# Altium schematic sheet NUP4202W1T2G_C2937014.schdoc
size 127 x 101 mm
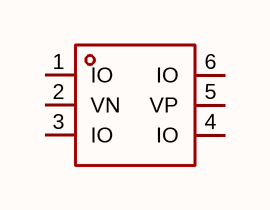
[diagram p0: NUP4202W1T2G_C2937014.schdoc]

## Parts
D?  nup4202w1t2g_c2937014  [SOT-363-6_L2.0-W1.3-P0.65-LS2.1-BL]  (value not drawn)

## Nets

Not connected (* = marked no-connect by the designer): D? 1(IO) 2(VN) 3(IO) 4(IO) 5(VP) 6(IO)

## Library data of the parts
D? = nup4202w1t2g_c2937014: 极性:单向;反向截止电压(Vrwm):5V;钳位电压:16V；17V;峰值脉冲电流(Ipp):4.5A@8/20us;峰值脉冲功率(Ppp):250W;击穿电压:9.5V;; Manufacturer: TECH PUBLIC(台舟); AddInBom: yes; ModelId: 600d0067f956474aba900c417738e59b; ModelName: SOT-363-6_L2.0-W1.25-LS2.1-BL; ModelTransform: 78.74,82.677,0,0,0,0,0,0,0; Polarity: 单向; Reverse Stand-Off Voltage (Vrwm): 5V; Peak Pulse Power Dissipation (Ppp): 250W; Voltage - Breakdown: 9.5V; Reverse Leakage Current (Ir): 100nA; Number of Channels: 四路; level of protection: IEC 61000-4-2；IEC 61000-4-4；IEC 61000-4-5; Type: ESD; Junction Capacitance: 0.6pF；0.3pF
